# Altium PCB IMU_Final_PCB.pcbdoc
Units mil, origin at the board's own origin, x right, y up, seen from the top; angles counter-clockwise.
Board outline 1676.37 x 1400 mil, 2 copper layers (Top Layer, Bottom Layer); 19 components, 12 nets, 72 pads, 31 vias.
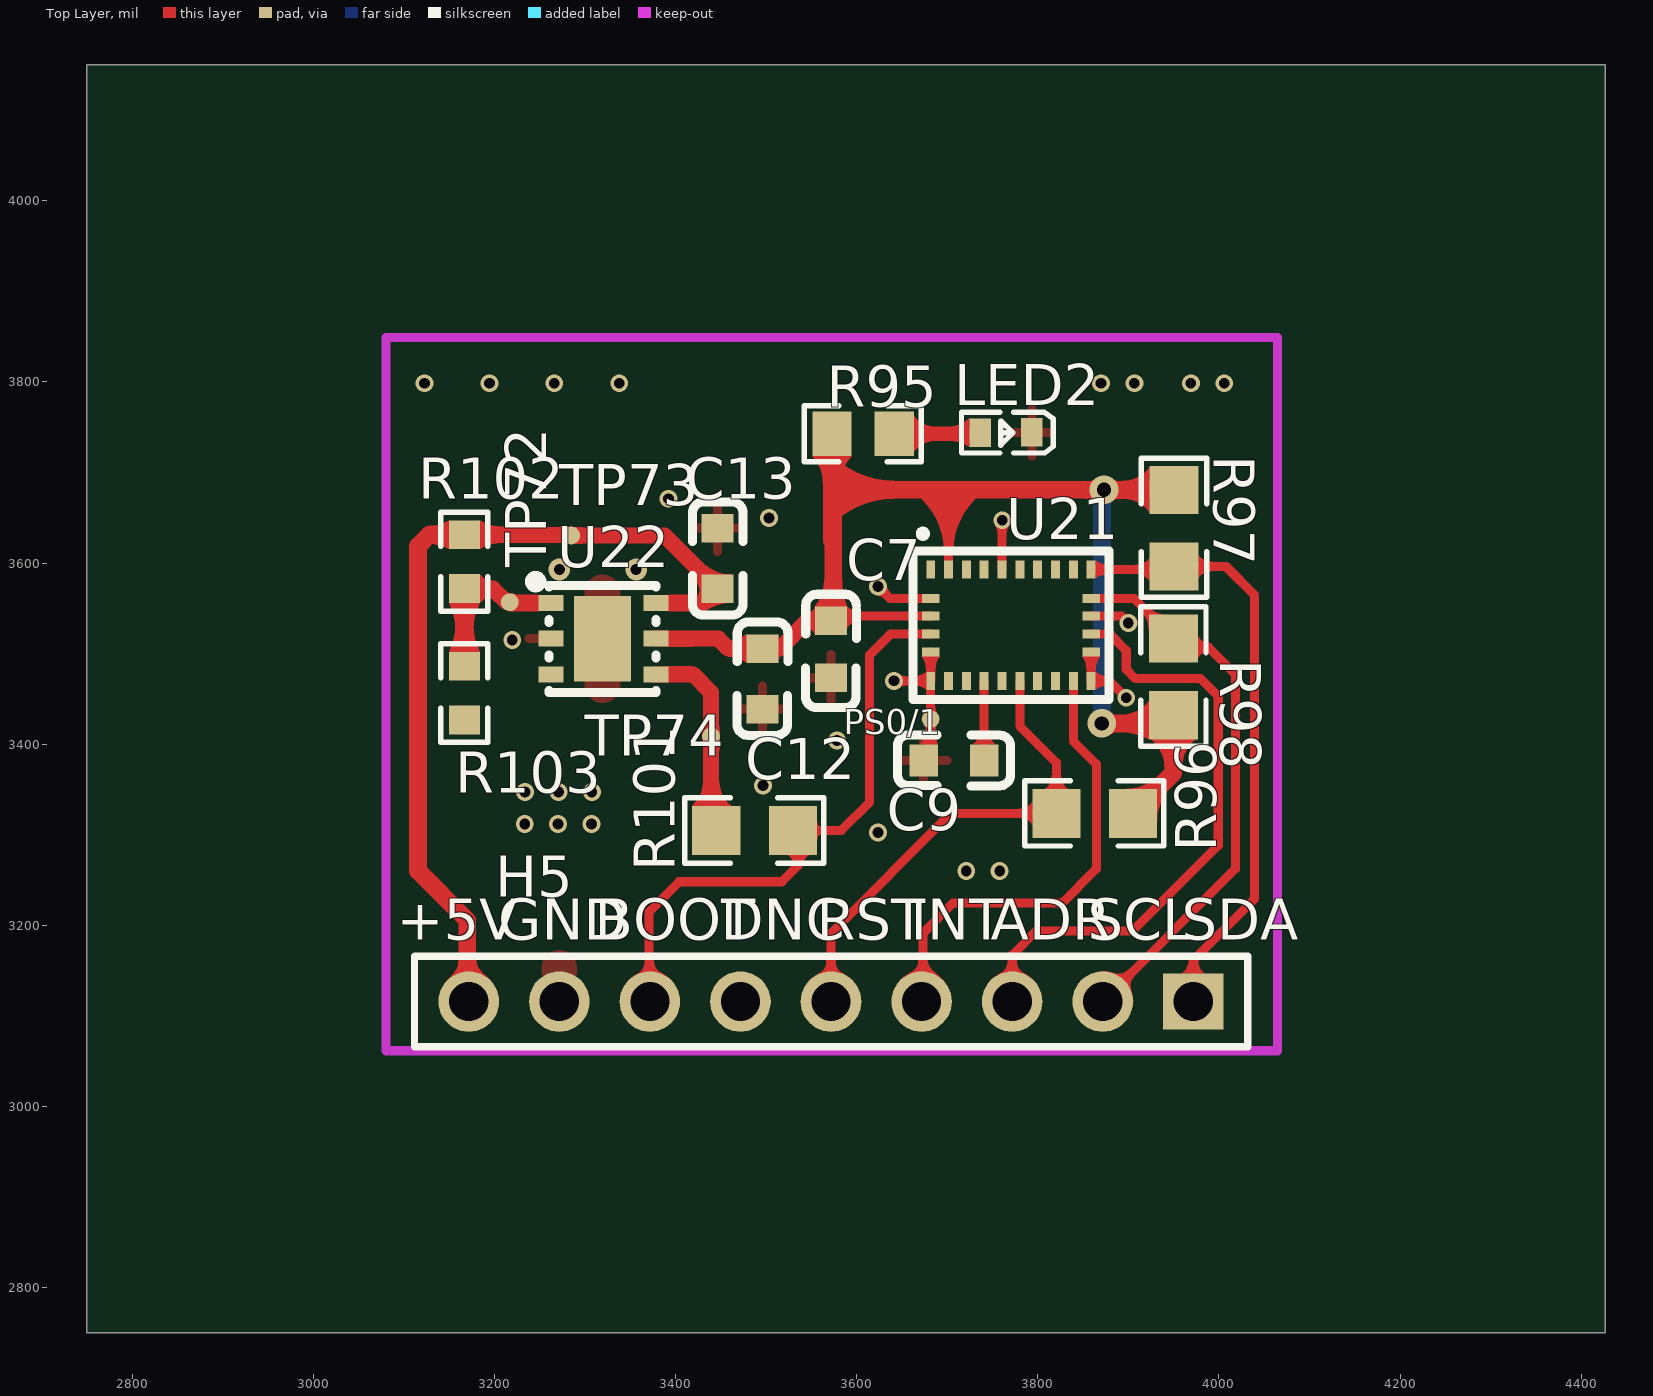
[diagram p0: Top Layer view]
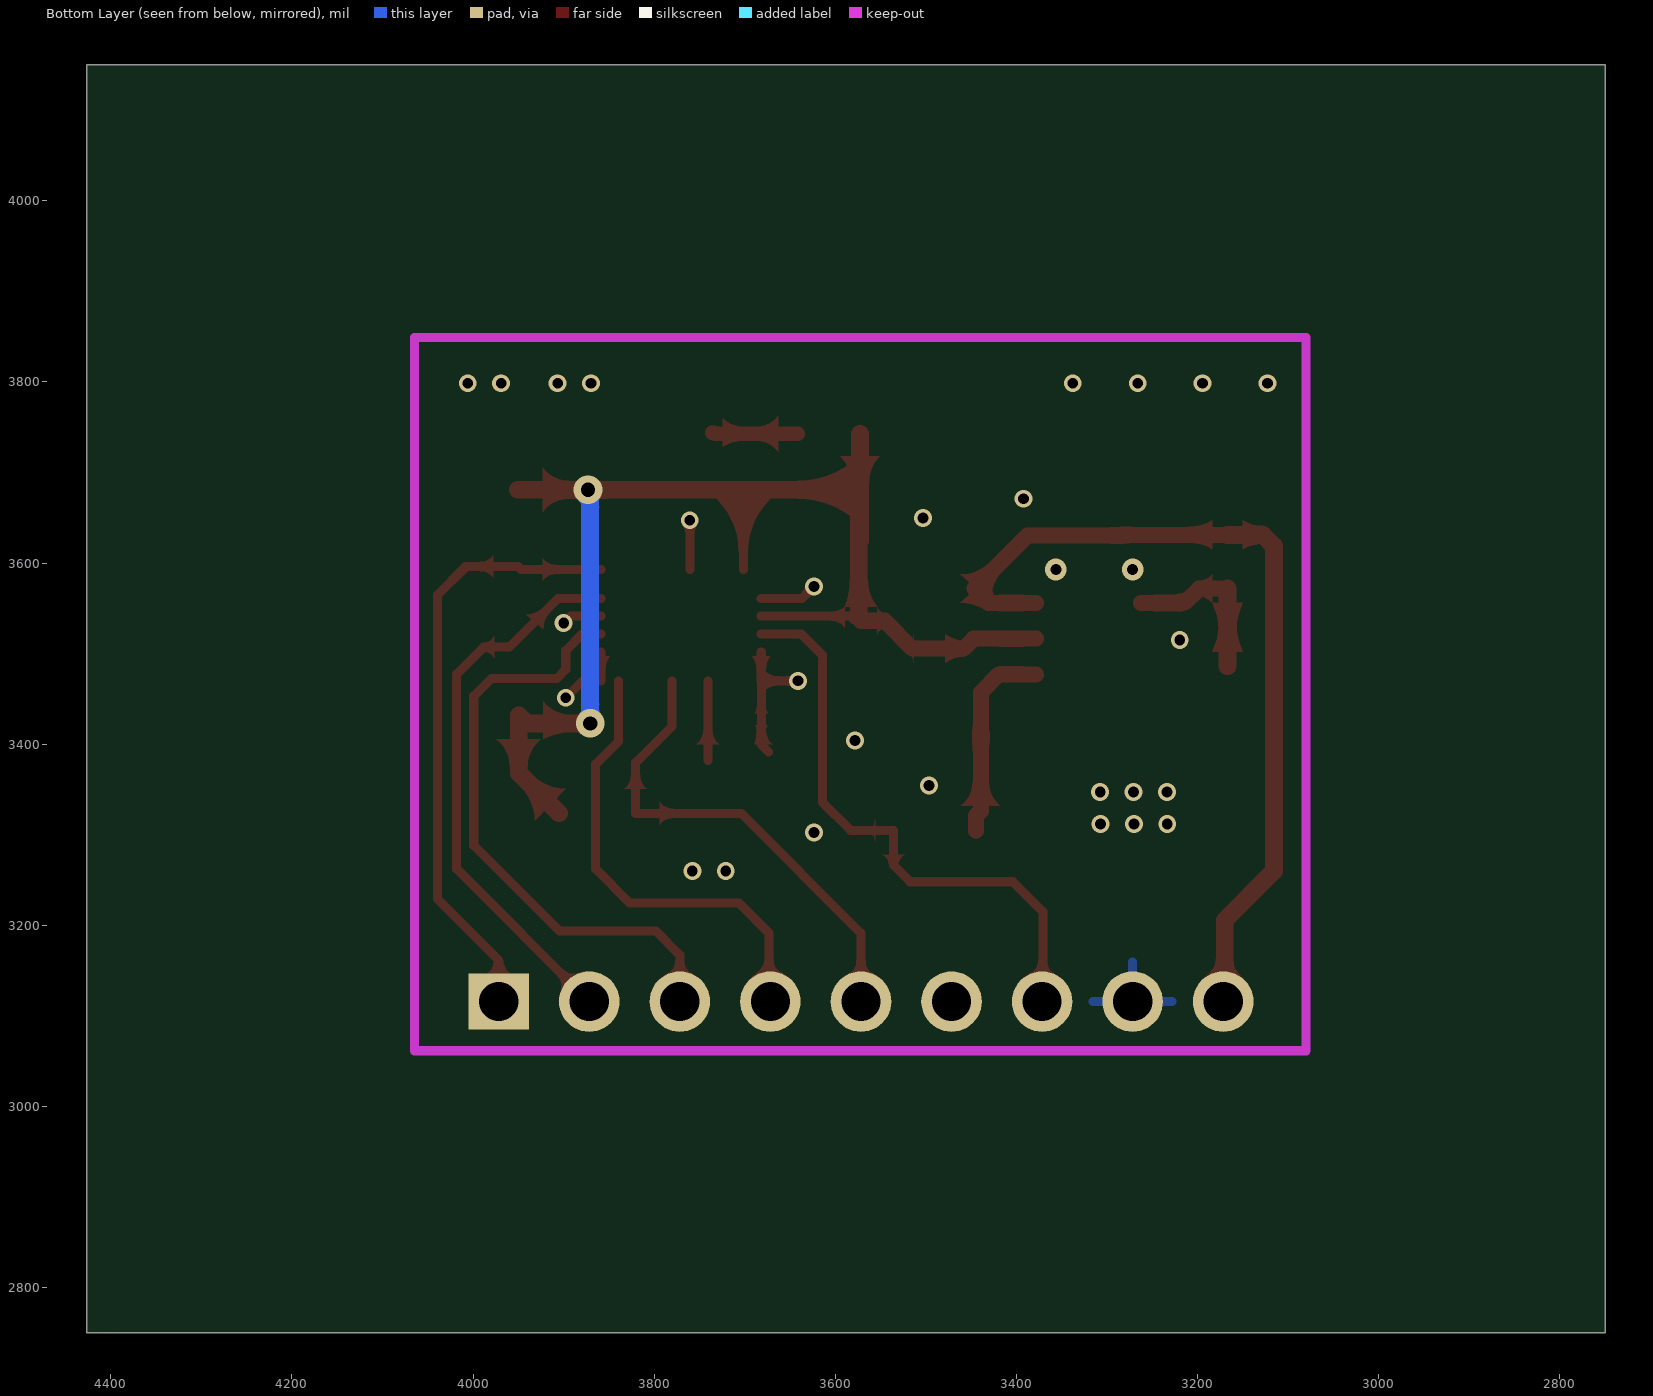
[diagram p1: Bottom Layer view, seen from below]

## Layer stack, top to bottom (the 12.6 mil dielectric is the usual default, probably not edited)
Top Layer: signal copper (thickness not stored)
Dielectric: dielectric 12.6, FR-4, Dk 4.8
Bottom Layer: signal copper (thickness not stored)

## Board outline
4426.37,2750 2750,2750 2750,4150 4426.37,4150

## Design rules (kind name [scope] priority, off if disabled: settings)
Clearance copperThickness1oz [All] p1: gap=7 ignorepadtopadclearanceinfootprint=FALSE except(4: Track-Track; 6: Track-SMDPad SMDPad-SMDPad Track-THPad SMDPad-THPad THPad-THPad Track-Via SMDPad-Via THPad-Via Via-Via SMDPad-Fill THPad-Fill Via-Fill Fill-Fill Track-Region SMDPad-Region THPad-Region Via-Region Region-Region Track-Poly SMDPad-Poly THPad-Poly Via-Poly Fill-Poly Region-Poly Poly-Poly Track-Text SMDPad-Text THPad-Text Via-Text Fill-Text Region-Text Poly-Text Text-Text; 6.9: Track-Hole SMDPad-Hole THPad-Hole Via-Hole Fill-Hole Region-Hole Poly-Hole Text-Hole Sheet-Hole; 11.8: Track-Fill Fill-Region Track-Sheet SMDPad-Sheet THPad-Sheet Via-Sheet Fill-Sheet Region-Sheet Poly-Sheet Text-Sheet)
Clearance copperThickness2oz [All] p1: gap=7 ignorepadtopadclearanceinfootprint=FALSE except(6: Track-SMDPad SMDPad-SMDPad Track-THPad SMDPad-THPad THPad-THPad Track-Via SMDPad-Via THPad-Via Via-Via SMDPad-Fill THPad-Fill Via-Fill Fill-Fill Track-Region SMDPad-Region THPad-Region Via-Region Region-Region Track-Poly SMDPad-Poly THPad-Poly Via-Poly Fill-Poly Region-Poly Poly-Poly Track-Text SMDPad-Text THPad-Text Via-Text Fill-Text Region-Text Poly-Text Text-Text; 6.9: Track-Hole SMDPad-Hole THPad-Hole Via-Hole Fill-Hole Region-Hole Poly-Hole Text-Hole Sheet-Hole; 8: Track-Track; 11.8: Track-Fill Fill-Region Track-Sheet SMDPad-Sheet THPad-Sheet Via-Sheet Fill-Sheet Region-Sheet Poly-Sheet Text-Sheet)
DiffPairsRouting differentialPair [All] p1: maxuncoupledlength=10 maxlimit=6 mostfreqgap=6 toplayer_minwidth=5 toplayer_prefwidth=10 toplayer_maxwidth=100 bottomlayer_minwidth=5 bottomlayer_prefwidth=10 bottomlayer_maxwidth=100
PasteMaskExpansion pasteMaskExpansion [All] p1:
PlaneConnect innerPlane [All] p1: planeconnectstyle=Relief reliefexpansion=20 reliefentries=4 reliefconductorwidth=10 reliefairgap=10
PolygonConnect copperRegion [All] p1: connectstyle=Relief reliefentries=4 reliefconductorwidth=10 polygonreliefangle="90 Angle" airgapwidth=10
RoutingVias viaSize [All] p1: viastyle="Through Hole" holewidth=12.0078 minholewidth=11.811 maxholewidth=248.0314 width=24.0158 minwidth=19.685 maxwidth=393.7008
SolderMaskExpansion solderMaskExpansion [All] p1: useseparateexpansions=TRUE expansion=2 expansionbottom=2
Width copperThickness1oz [All] p1: maxlimit=100 minlimit=5 preferedwidth=10
Width copperThickness2oz [All] p1: maxlimit=100 minlimit=8 preferedwidth=10

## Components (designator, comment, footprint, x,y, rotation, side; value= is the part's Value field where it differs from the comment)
C7 "CAP_0201" Cbst2 3571.65,3500.79 r90 top
C9 "CAP_0201" C9 3705.32,3381.97 r0 top
C12 "CAP_0201" C9 3496.06,3470.08 r90 top
C13 "CAP_0201" C9 3446.46,3607.09 r270 top
H5 "HDR-F_2.54_1x9P" HDR-TH_9P-P2.54-V-F-1 3571.65,3115.75 r180 top
LED2 "TLMS1100-GS08" "LED2 RED" 3767.72,3744.09 r180 top
PS0/1 "Test-Point" Test-Point-0.5mm 3681.62,3427.73 r0 top
R95 "Res_0201" Rtrip 3611.85,3742.68 r180 top
R96 "Res_0201" "0805 dany2" 3859.84,3323.62 r0 top
R97 "Res_0201" "0805 dany2" 3950.32,3641.42 r270 top
R98 "Res_0201" "0805 dany2" 3949.6,3477.16 r270 top
R101 "Res_0201" "0805 dany2" 3484.25,3304.72 r0 top
R102 "Res_0201" R0603 3166.85,3601.42 r270 top
R103 "Res_0201" R0603 3166.85,3456.42 r270 top
TP72 "Test-Point" Test-Point-0.5mm 3216.99,3556.72 r0 top
TP73 "Test-Point" Test-Point-0.5mm 3284.91,3630.38 r0 top
TP74 "Test-Point" Test-Point-0.5mm 3439.21,3408.62 r0 top
U21 "BNO055" LGA-28_L5.2-W3.8-P0.50-BL 3770.32,3531.42 r270 top
U22 "NCP708MU330TAG" DFN-6_L3.0-W3.0-P0.95-LS3.1-BL-EP 3320.32,3516.42 r270 top

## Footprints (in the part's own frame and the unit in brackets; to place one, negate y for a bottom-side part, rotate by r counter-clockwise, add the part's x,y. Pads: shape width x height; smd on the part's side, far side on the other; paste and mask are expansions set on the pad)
"0805 dany2" [mm]
  rect 1.35x1.377 smd: 1(-1,0) 2(1.15,0)
  silkscreen extent -1.89,-0.92 2.02,0.92
C9 [mm]
  rect 0.8x0.9 smd: 1(-0.8,0) 2(0.9,0)
  silkscreen extent -1.53,-0.71 1.64,0.72
Cbst2 [mm]
  rect 0.8x0.9 smd: 1(-0.7,0) 2(0.9,0)
  silkscreen extent -1.53,-0.71 1.64,0.72
DFN-6_L3.0-W3.0-P0.95-LS3.1-BL-EP [mm]
  rect 0.45x0.701 smd: 1(-1.001,-1.476) 2(0,-1.476) 3(1.001,-1.476) 4(1.001,1.476) 5(0,1.476) 6(-1.001,1.476)
  rect 2.4x1.6 smd: 7(0,-0.025)
  silkscreen extent -1.75,-2.05 1.5,1.47
HDR-TH_9P-P2.54-V-F-1 [mm]
  rect 1.7x1.575 hole 1.1: 1(-10.16,0)
  round 1.7 hole 1.1: 2(-7.62,0) 3(-5.08,0) 4(-2.54,0) 5(0,0) 6(2.54,0) 7(5.08,0) 8(7.62,0) 9(10.16,0)
  silkscreen extent -11.68,-1.27 11.68,1.27
"LED2 RED" [mm]
  rect 0.6x0.8 smd: 1(-0.65,-0.003) 2(0.8,0.003)
  silkscreen extent -1.25,-0.57 1.32,0.58
LGA-28_L5.2-W3.8-P0.50-BL [mm]
  rect 0.5x0.25 smd: 1(-1.563,-2.25) 6(1.563,-2.25) 7(1.563,-1.75) 8(1.563,-1.25) 9(1.563,-0.75) 10(1.563,-0.25) 11(1.563,0.25) 12(1.563,0.75) 13(1.563,1.25) 14(1.563,1.75) 15(1.563,2.25) 20(-1.563,2.25) 21(-1.563,1.75) 22(-1.563,1.25) 23(-1.563,0.75) 24(-1.563,0.25) 25(-1.563,-0.25) 26(-1.563,-0.75) 27(-1.563,-1.25) 28(-1.563,-1.75)
  rect 0.25x0.5 smd: 2(-0.75,-2.25) 3(-0.25,-2.25) 4(0.25,-2.25) 5(0.75,-2.25) 16(0.75,2.25) 17(0.25,2.25) 18(-0.25,2.25) 19(-0.75,2.25)
  silkscreen extent -2.66,-2.75 2.08,2.75
R0603 [mil]
  rect 31.75x34.02 smd: 1(-29.66,0) 2(29.66,0)
  silkscreen extent -55,-26 55,26
Rtrip [mm]
  rect 1.1x1.25 smd: 1(-0.753,0) 2(0.997,0)
  silkscreen extent -1.51,-0.79 1.77,0.79
Test-Point-0.5mm [mm]
  round 0.5 smd: 1(0,0)

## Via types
v1: diameter 19.68, hole 11.81, Top Layer to Bottom Layer, 27 vias
v2: diameter 31.5, hole 15.75, Top Layer to Bottom Layer, 2 vias
v3: diameter 24.02, hole 12.01, Top Layer to Bottom Layer, 2 vias

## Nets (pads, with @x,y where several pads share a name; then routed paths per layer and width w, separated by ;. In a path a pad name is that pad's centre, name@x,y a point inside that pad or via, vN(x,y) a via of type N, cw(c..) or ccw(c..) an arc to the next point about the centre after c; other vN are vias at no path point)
$1N1002: C9.2 U21.9 | length 87.9
  Top Layer w10: C9.2@3740.79,3382.02 U21.9
$1N2238: LED2.2 R95.1 | length 95.3
  Top Layer w15.75: R95.1 3732.6,3742.68 3733.88,3743.96 LED2.2
+5V: C13.2 H5.9 R102.1 TP73.1 U22.6 | length 961.3
  Top Layer w17.72: R102.1 3284.21,3631.08 TP73.1 3387.73,3630.38 C13.2 3430.62,3555.82 U22.6
  Top Layer w19.68: R102.1 3127.93,3631.08 3115.75,3618.9 3115.75,3259.84 3170.08,3205.51 3170.08,3117.32 H5.9
BOOT: H5.7 R101.2 U21.4 | length 655.7
  Top Layer w10: H5.7 3370.87,3116.53 3370.87,3214.96 3403.94,3248.03 3517.32,3248.03 3535.59,3266.3 3535.59,3304.72 3557.28,3304.72 ; 3557.72,3304.29 3557.28,3304.72 ; U21.4 3637.32,3521.57 3614.17,3498.42 3614.17,3335.98 3582.91,3304.72 3557.28,3304.72
EN3V3: R102.2 R103.1 TP72.1 U22.1 | length 188.5
  Top Layer w17.72: R102.2 3198.32,3571.76 3213.36,3556.72 TP72.1 TP72.1@3217.89,3555.82 ; TP72.1@3216.99,3555.82 TP72.1@3217.89,3555.82 ; U22.1 TP72.1@3217.89,3555.82
  Top Layer w19.68: R103.1 R102.2
GND: C7.1 C9.1 C12.1 C13.1 H5.8 LED2.1 PS0/1.1 R103.2 U21.2 U21.5 U21.6 U21.15 U21.16 U21.18 U21.25 U22.2 U22.7 | length 395.2
  Top Layer w10: v1(3623.62,3574.01) 3636.69,3560.94 U21.2 ; v1@3640.9,3470.08 v1(3641.1,3469.88) U21.6 ; C9.1@3673.82,3391.42 3681.73,3399.34 U21.6 ; U21.5 U21.6 ; U21.25 3760.48,3647.09 v1(3760.63,3647.24) ; U21.16 U21.15 3878.93,3469.88 v1(3897.64,3451.18) ; U21.18 3892.59,3541.26 v1(3900,3533.86)
  other v1: 3720.94,3259.84 3757.79,3259.84 3623.62,3302.36 3233.39,3311.81 3270.24,3311.81 3307.09,3311.81 3233.86,3347.24 3270.71,3347.24 3307.56,3347.24 3496.53,3354.33 3578.27,3403.94 3219.68,3514.96 3503.15,3649.61 3392.13,3670.86 3122.83,3798.42 3194.49,3798.42 3266.14,3798.42 3337.79,3798.42 3869.76,3798.42 3906.61,3798.42 3968.97,3798.42 4005.82,3798.42
  other v3: 3271.65,3592.91 3356.49,3592.91
GPIO6: H5.5 R96.1 U21.11 | length 542.2
  Top Layer w10: H5.5 3571.65,3191.34 3703.94,3323.62 R96.1 3820.47,3379.53 3780.16,3419.84 U21.11
I2C_ADRESS_SELECT: H5.3 U21.17 | length 674.6
  Top Layer w10: H5.3 3771.65,3166.93 3798.42,3193.7 3904.72,3193.7 3999.21,3288.19 3999.21,3452.99 3979.76,3472.44 3907.64,3472.44 3897.64,3482.44 3897.64,3503.15 3879.2,3521.58 U21.17
INT: H5.4 U21.14 | length 509.5
  Top Layer w10: H5.4@3671.61,3121.42 3673.23,3123.03 3673.23,3191.34 3706.3,3224.41 3826.77,3224.41 3864.57,3262.2 3864.57,3377.95 3839.22,3403.3 U21.14
SCK/SCL: H5.2 R98.1 U21.19 | length 616
  Top Layer w10: U21.19 3905.97,3560.95 3959.84,3507.09 3988.19,3507.09 4018.11,3477.16 4018.11,3262.2 H5.2
SDI/SDA: H5.1 R97.2 U21.20 | length 671.7
  Top Layer w10: U21.20 3947.13,3592.95 R97.2 4007.79,3596.14 4039.37,3564.57 4039.37,3229.13 3971.65,3161.42 H5.1
VDDIO: 
pads on no net: C7.2 C12.2 H5.6 R95.2 R96.2 R97.1 R98.2 R101.1 TP74.1 U21.1 U21.3 U21.7 U21.8 U21.10 U21.12 U21.13 U21.21 U21.22 U21.23 U21.24 U21.26 U21.27 U21.28 U22.3 U22.4 U22.5
copper on no net: | length 1738.2
  Top Layer w10: 3571.65,3536.22 3576.7,3541.26 3681.74,3541.26 ; 3701.42,3592.95 3701.42,3678.93 3703.27,3680.79
  Top Layer w17.72: 3378.41,3477.02 3419.29,3477.02 3439.37,3456.94 3439.37,3326.42 3444.88,3320.91 3444.88,3304.72 ; 3378.41,3516.42 3447.36,3516.42 3458.27,3505.51 3491.33,3505.51 3514.96,3505.51 3545.67,3536.22 3571.65,3536.22
  Top Layer w19.68: 3572.61,3742.68 3572.61,3625.02 3574.01,3623.62 ; 3576.7,3541.26 3574.01,3543.94 3574.01,3623.62 ; v2(3870.71,3422.83) 3940.55,3422.83 3949.6,3431.89 3949.6,3368.11 3905.12,3323.62 ; 3950.32,3680.79 v2(3873.07,3680.79) 3703.27,3680.79 3576.85,3680.79 3574.01,3677.95 3574.01,3623.62
  Bottom Layer w19.68: v2(3870.71,3422.83) 3870.71,3678.43 v2(3873.07,3680.79)

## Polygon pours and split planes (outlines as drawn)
no net on Top Layer (solid, remove dead copper): 3359.06,3462.99 3399.21,3462.99 3399.21,3531.5 3359.06,3531.5
GND on Bottom Layer (solid, remove dead copper, pour order 4): 3000,3033.07 4176.37,3033.07 4176.37,3900 3000,3900
GND on Top Layer (solid, remove dead copper, pour order 2): 3011.81,3000 4105.51,3000 4105.51,3890.55 3011.81,3890.55

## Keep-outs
Board Outline Layer:
  lines w10: 3080.32,3061.42 4064.57,3061.42 4064.57,3848.82 3080.32,3848.82 3080.32,3061.42

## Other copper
Top Layer:
  region: 3545.67,3527.36 3545.67,3545.08 ccw(c3545.67,3553.48) 3553.94,3551.97 3553.94,3520.47 ccw(c3545.67,3518.95)
  region: 3604.37,3546.26 3604.37,3536.26 ccw(c3604.37,3517.51) 3589.37,3528.76 3589.37,3551.97 ccw(c3604.37,3568.84)
  region: 3564.17,3581.49 3583.86,3581.49 ccw(c3665.7,3581.49) 3589.37,3551.97 3553.94,3551.97 ccw(c3516.47,3581.49)
  region net $1N1002: 3735.79,3414.69 3745.79,3414.69 ccw(c3764.54,3414.69) 3753.29,3399.69 3728.29,3399.69 ccw(c3717.04,3414.69)
  region net GND: 3676.73,3414.69 3686.73,3414.69 ccw(c3727.83,3414.69) 3689.56,3399.69 3669.23,3399.69 ccw(c3657.98,3414.69)
  region: 3458.27,3496.65 3458.27,3514.37 ccw(c3458.27,3547.05) 3478.34,3521.26 3478.34,3489.76 ccw(c3458.27,3463.97)
  region: 3514.96,3514.37 3514.96,3496.65 ccw(c3534.41,3489.76) 3513.77,3489.76 3513.77,3521.26 ccw(c3534.41,3521.26)
  region net +5V: 3436.89,3549.55 3424.36,3562.08 ccw(c3365.3,3585.26) 3428.74,3585.26 3462.03,3555.91 ccw(c3462.03,3502.97)
  region net +5V: 3419.35,3586.24 3433.84,3596.8 ccw(c3462.03,3634.38) 3462.03,3587.4 3428.74,3558.05 ccw(c3381.77,3558.05)
  region net $1N2238: 3700.81,3734.8 3700.81,3750.55 ccw(c3700.81,3785.61) 3724.43,3759.7 3724.43,3728.21 ccw(c3700.81,3689.2)
  region net GND: 3676.73,3441.26 3686.73,3441.1 3686.89,3439.35 3687.35,3437.46 3688.08,3435.66 3689.03,3434.21 3674.36,3434.37 3675.34,3435.81 3676.09,3437.61 3676.56,3439.5
  region net GND: 3686.73,3414.36 3676.73,3414.2 3676.56,3415.96 3676.09,3417.85 3675.34,3419.64 3674.36,3421.09 3689.03,3421.25 3688.08,3419.8 3687.35,3418 3686.89,3416.11
  region: 3582.46,3688.54 3562.77,3688.54 ccw(c3519.96,3688.54) 3550.96,3718.07 3594.27,3718.07 ccw(c3625.27,3688.54)
  region net $1N2238: 3686.79,3750.55 3686.79,3734.8 ccw(c3686.79,3705.28) 3663.16,3722.99 3663.16,3762.36 ccw(c3686.79,3780.08)
  region: 3928.74,3361.17 3942.13,3346.72 ccw(c3983.89,3315.4) 3931.69,3315.4 3897.42,3350.73 ccw(c3897.42,3402.93)
  region net GPIO6: 3778.9,3318.62 3778.9,3328.62 ccw(c3778.9,3347.37) 3793.9,3336.12 3793.9,3311.12 ccw(c3778.9,3299.87)
  region net GPIO6: 3815.47,3365.73 3825.47,3365.73 ccw(c3844.22,3365.73) 3832.97,3350.73 3807.97,3350.73 ccw(c3796.72,3365.73)
  region net SDI/SDA: 3908.21,3587.95 3908.21,3597.95 ccw(c3908.21,3616.7) 3923.21,3605.45 3923.21,3580.45 ccw(c3908.21,3569.2)
  region net SDI/SDA: 3992.42,3601.14 3992.42,3591.14 ccw(c3992.42,3572.39) 3977.42,3583.64 3977.42,3608.64 ccw(c3992.42,3619.89)
  region: 3893.68,3670.94 3893.68,3690.63 ccw(c3893.68,3727.54) 3923.21,3705.39 3923.21,3656.18 ccw(c3893.68,3634.04)
  region: 3892.97,3412.99 3892.97,3432.68 ccw(c3892.97,3469.59) 3922.5,3447.44 3922.5,3405.31 ccw(c3892.97,3352.37)
  region: 3959.45,3375.79 3939.76,3375.79 ccw(c3902.85,3375.79) 3925,3405.31 3974.21,3405.31 ccw(c3996.36,3375.79)
  region net SCK/SCL: 3917.19,3542.66 3925.59,3548.41 ccw(c3941.49,3569.63) 3941.49,3543.11 3922.5,3526.75 ccw(c3895.98,3526.75)
  region net SCK/SCL: 3988.19,3512.09 3988.19,3502.09 ccw(c3988.19,3489.56) 3976.71,3494.59 3976.71,3519.59 ccw(c3988.19,3524.62)
  region net BOOT: 3540.59,3266.3 3530.59,3266.3 ccw(c3518.3,3266.3) 3523.09,3277.62 3548.09,3277.62 ccw(c3552.88,3266.3)
  region net BOOT: 3557.28,3309.72 3557.28,3299.72 ccw(c3580.48,3292.22) 3556.1,3292.22 3556.1,3317.22 ccw(c3580.48,3317.22)
  region: 3430.51,3358.41 3448.23,3358.41 ccw(c3481.45,3358.41) 3461.51,3331.83 3418.31,3331.83 ccw(c3395.48,3358.41)
  region net EN3V3: 3198.32,3580.62 3198.32,3562.9 ccw(c3198.32,3544.49) 3183.86,3555.88 3183.86,3587.63 ccw(c3198.32,3599.03)
  region net EN3V3: 3176.69,3526.35 3157.01,3526.35 ccw(c3092.59,3526.35) 3149.84,3555.88 3183.86,3555.88 ccw(c3241.11,3526.35)
  region net +5V: 3127.93,3621.23 3127.93,3640.92 ccw(c3127.93,3683.73) 3149.84,3646.95 3149.84,3615.2 ccw(c3127.93,3578.42)
  region net +5V: 3210.43,3639.94 3210.43,3622.22 ccw(c3210.43,3568.39) 3183.86,3615.2 3183.86,3646.95 ccw(c3210.43,3693.76) 3210.43,3639.94
  region net EN3V3: 3157.01,3531.48 3176.69,3531.48 ccw(c3241.11,3531.48) 3183.86,3501.95 3149.84,3501.95 ccw(c3092.59,3531.48)
  region net EN3V3: 3199.59,3557.96 3211.94,3570.66 3214.44,3567.91 3215.77,3566.98 3216.59,3566.69 3217.56,3566.55 3207.19,3555.81 3206.87,3556.65 3206.18,3557.07 3205.21,3557.22 3204.06,3557.2 3201.6,3557.17 3200.49,3557.4
  region net EN3V3: 3229.7,3564.68 3229.7,3546.96 3222.89,3546.82 3219.2,3546.79 3216.09,3546.92 3217.89,3566.52 3221.15,3566.04 3223.79,3565.43 3226.44,3564.9
  region net +5V: 3296.72,3639.24 3296.72,3621.52 3292.52,3621.37 3288.97,3621.03 3284.91,3620.54 3284.91,3640.22 3288.97,3639.73 3292.52,3639.39
  region net +5V: 3272.4,3622.22 3272.4,3639.94 3279.01,3640.18 3282.36,3640.28 3285.6,3640.2 3284.21,3620.56 3280.73,3621 3278.31,3621.55 3275.9,3622.02
  region: 3430.51,3420.59 3448.23,3420.28 3448.37,3416.77 3448.68,3414.37 3448.96,3411.98 3449.05,3408.47 3429.37,3408.78 3429.59,3412.29 3429.98,3414.68 3430.35,3417.08
  region: 3448.23,3392.05 3430.51,3391.73 3430.35,3396.71 3429.99,3400.1 3429.61,3403.49 3429.37,3408.47 3449.05,3408.78 3448.98,3403.81 3448.69,3400.41 3448.38,3397.02
  region net GND: 3686.74,3481.97 3676.74,3481.97 ccw(c3651.09,3481.97) 3671.9,3496.97 3691.58,3496.97 ccw(c3712.39,3481.97)
  region net GND: 3661.81,3464.88 3661.81,3474.88 ccw(c3661.81,3500.54) 3676.81,3479.72 3676.81,3460.04 ccw(c3661.81,3439.23)
  region net GND: 3878.82,3474.88 3878.82,3464.88 ccw(c3878.82,3439.23) 3863.82,3460.04 3863.82,3479.72 ccw(c3878.82,3500.54)
  region net GND: 3863.9,3481.97 3853.9,3481.97 ccw(c3828.25,3481.97) 3849.06,3496.97 3868.74,3496.97 ccw(c3889.55,3481.97)
  region net SDI/SDA: 3878.82,3597.95 3878.82,3587.95 ccw(c3878.82,3562.3) 3863.82,3583.11 3863.82,3602.79 ccw(c3878.82,3623.61)
  region net EN3V3: 3221.84,3546.96 3221.84,3564.68 3248.41,3564.68 3248.41,3546.96
  region: 3418.79,3485.88 3418.79,3468.16 3392.22,3468.16 3392.22,3485.88
  region: 3418.79,3525.28 3418.79,3507.56 3392.22,3507.56 3392.22,3525.28
  region net +5V: 3418.79,3564.68 3418.79,3546.96 3392.22,3546.96 3392.22,3564.68
  region net SDI/SDA: 3966.65,3161.42 3976.65,3161.42 ccw(c3994.75,3161.42) 3984.15,3146.75 3959.15,3146.75 ccw(c3948.56,3161.42)
  region net SCK/SCL: 3900.46,3151.62 3907.53,3144.55 3905.77,3142.63 3904.42,3140.81 3903.44,3139.07 3902.8,3137.4 3902.44,3135.76 3902.32,3134.14 3902.4,3132.51 3902.64,3130.85 3903.42,3127.36 3904.31,3123.49 3904.98,3119.06 3905.11,3116.58 3905.07,3113.89 3869.79,3149.16 3872.48,3149.21 3874.96,3149.07 3879.39,3148.41 3883.27,3147.52 3886.76,3146.74 3888.41,3146.5 3890.04,3146.42 3891.66,3146.53 3893.3,3146.89 3894.98,3147.54 3896.71,3148.51 3898.53,3149.86
  region net I2C_ADRESS_SELECT: 3766.65,3161.48 3776.65,3161.48 3776.77,3158.88 3777.1,3156.64 3777.64,3154.72 3778.37,3153.08 3779.27,3151.67 3780.33,3150.44 3781.54,3149.34 3782.88,3148.34 3785.9,3146.42 3789.27,3144.32 3792.88,3141.65 3794.73,3139.99 3796.6,3138.06 3746.71,3138.06 3748.58,3139.99 3750.43,3141.65 3754.03,3144.32 3757.4,3146.42 3760.42,3148.34 3761.76,3149.34 3762.97,3150.44 3764.04,3151.67 3764.94,3153.08 3765.67,3154.72 3766.2,3156.64 3766.54,3158.88
  region net INT: 3668.23,3162.63 3678.23,3160.28 3678.39,3158.82 3678.86,3157.32 3679.6,3155.78 3680.58,3154.22 3683.08,3151.07 3686.1,3147.93 3692.54,3141.95 3695.39,3139.26 3697.62,3136.86 3647.79,3139.21 3649.7,3141.02 3651.6,3142.6 3655.29,3145.2 3658.75,3147.34 3661.84,3149.35 3663.21,3150.41 3664.45,3151.55 3665.54,3152.83 3666.47,3154.28 3667.22,3155.95 3667.77,3157.87 3668.11,3160.08
  region net GPIO6: 3566.65,3161.48 3576.65,3161.48 3576.77,3158.88 3577.1,3156.64 3577.64,3154.72 3578.37,3153.08 3579.27,3151.67 3580.33,3150.44 3581.54,3149.34 3582.88,3148.34 3585.9,3146.42 3589.27,3144.32 3592.88,3141.65 3594.73,3139.99 3596.6,3138.06 3546.71,3138.06 3548.58,3139.99 3550.43,3141.65 3554.03,3144.32 3557.4,3146.42 3560.42,3148.34 3561.76,3149.34 3562.97,3150.44 3564.04,3151.67 3564.94,3153.08 3565.67,3154.72 3566.2,3156.64 3566.54,3158.88
  region net BOOT: 3365.87,3160.89 3375.87,3162.06 3375.98,3159.49 3376.32,3157.26 3376.86,3155.34 3377.6,3153.69 3378.52,3152.26 3379.59,3151 3380.82,3149.88 3382.18,3148.85 3385.24,3146.89 3388.65,3144.77 3392.3,3142.13 3394.17,3140.51 3396.06,3138.64 3346.19,3137.46 3348.03,3139.46 3349.86,3141.16 3353.42,3143.86 3359.72,3147.82 3361.04,3148.79 3362.23,3149.86 3363.28,3151.06 3364.17,3152.46 3364.89,3154.09 3365.42,3156 3365.75,3158.26
  region net +5V: 3160.24,3160.28 3179.92,3162.63 3180.01,3160.62 3180.27,3158.76 3180.69,3157.02 3181.26,3155.39 3181.97,3153.87 3182.8,3152.42 3184.8,3149.72 3187.16,3147.17 3189.79,3144.65 3195.52,3139.21 3145.69,3136.86 3148.4,3139.96 3151.03,3142.67 3153.49,3145.16 3155.69,3147.6 3157.55,3150.16 3158.33,3151.54 3158.99,3153.02 3159.52,3154.61 3159.91,3156.33 3160.15,3158.22
  region: 3851.55,3670.94 3851.55,3690.63 3854.69,3690.51 3857.49,3690.46 3858.8,3690.62 3860.08,3690.98 3861.33,3691.59 3862.58,3692.53 3862.58,3669.05 3861.33,3669.98 3860.08,3670.6 3858.8,3670.95 3857.49,3671.11 3854.69,3671.07
  region: 3894.6,3690.63 3894.6,3670.94 3891.46,3671.07 3888.66,3671.11 3887.35,3670.95 3886.07,3670.6 3884.82,3669.98 3883.57,3669.05 3883.57,3692.53 3884.82,3691.59 3886.07,3690.98 3887.35,3690.62 3888.66,3690.46 3891.46,3690.51
  region: 3892.23,3432.68 3892.23,3412.99 3889.1,3413.11 3886.3,3413.16 3884.98,3413 3883.71,3412.64 3882.46,3412.03 3881.21,3411.1 3881.21,3434.57 3882.46,3433.64 3883.71,3433.02 3884.98,3432.67 3886.3,3432.51 3889.1,3432.56
  region net GND: 3765.48,3633.68 3755.48,3633.9 3755.32,3635.65 3754.86,3637.54 3754.14,3639.34 3753.19,3640.79 3767.86,3640.57 3766.88,3639.13 3766.13,3637.34 3765.65,3635.44
  region net GND: 3636.67,3568.04 3629.6,3560.97 3628.24,3562.09 3626.57,3563.1 3624.78,3563.85 3623.07,3564.19 3633.45,3574.56 3633.79,3572.85 3634.54,3571.07 3635.54,3569.4
  region net GND: 3654.55,3474.88 3654.55,3464.88 3652.8,3464.72 3650.9,3464.25 3649.11,3463.51 3647.66,3462.55 3647.66,3477.22 3649.11,3476.25 3650.9,3475.52 3652.8,3475.05
  region: 3696.42,3611.89 ccw(c3613.06,3611.89) 3671.89,3670.94 3703.27,3680.79 3730.95,3670.94 ccw(c3789.78,3611.89) 3706.42,3611.89
  region: 3641.51,3670.94 ccw(c3641.51,3572.52) 3582.46,3651.26 3572.61,3680.79 3582.46,3710.31 ccw(c3641.51,3789.05) 3641.51,3690.63
Bottom Layer:
  region: 3880.56,3657.62 3860.87,3661.14 3861.08,3664.32 3861.36,3666.95 3861.35,3668.18 3861.15,3669.43 3860.69,3670.74 3859.89,3672.17 3883.11,3668.65 3882.01,3667.54 3881.26,3666.35 3880.79,3665.09 3880.54,3663.74 3880.47,3660.83
  region: 3860.87,3444.36 3880.56,3444.36 3880.43,3441.22 3880.39,3438.42 3880.55,3437.1 3880.9,3435.83 3881.52,3434.58 3882.45,3433.33 3858.97,3433.33 3859.91,3434.58 3860.52,3435.83 3860.88,3437.1 3861.04,3438.42 3860.99,3441.22

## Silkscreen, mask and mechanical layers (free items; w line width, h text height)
Top Silkscreen Layer:
  text "+5V" at 3092.13,3184.25 h45
  text "GND" at 3204.48,3184.25 h45
  text "BOOT" at 3310.73,3184.25 h45
  text "DNC" at 3449.69,3184.25 h45
  text "RST" at 3555.94,3184.25 h45
  text "INT" at 3659.79,3184.25 h45
  text "ADR" at 3747.75,3184.25 h45
  text "SCL" at 3855.2,3184.25 h45
  text "SDA" at 3959.05,3184.25 h45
